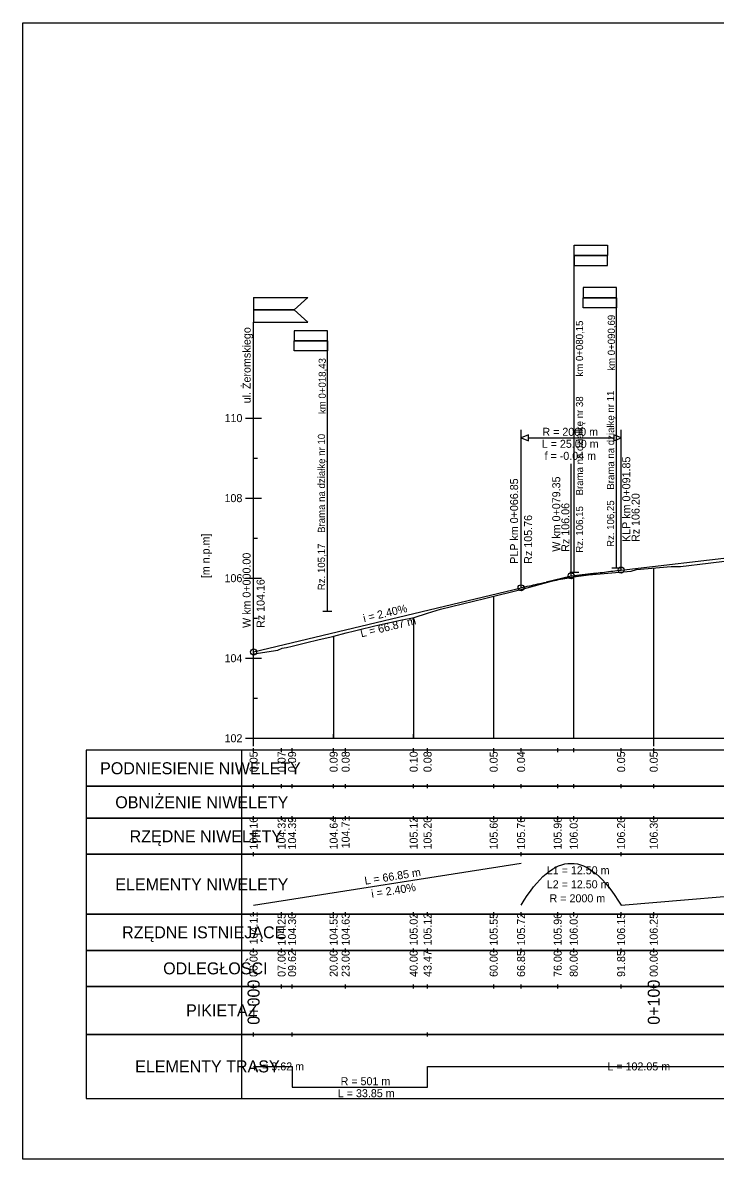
# Model space of a CAD drawing. Extents: x 7481207 to 7481727, y 5776531 to 5776815.
# Drawn here: x 7481207.5 to 7481380.5, y 5776530.9 to 5776814.9 of the extents above; entities that cross this region are included whole.
import ezdxf

# ---------------------------------------------------------------- set-up
doc = ezdxf.new("R2010")
doc.units = 0
for name, color, linetype in [('d_p_opisy_drog', 7, 'Continuous'), ('d_p_tabela', 7, 'Continuous'), ('opis niwelety', 7, 'Continuous'), ('prof_niweleta', 7, 'Continuous'), ('prof_odniesienie', 7, 'Continuous'), ('prof_os', 7, 'Continuous'), ('prof_tabela_txt', 7, 'Continuous'), ('ramka', 7, 'Continuous'), ('tabela_p', 7, 'Continuous'), ('tabela_txt_p', 7, 'Continuous'), ('teren', 7, 'Continuous'), ('zjazdy lewe', 7, 'Continuous'), ('zjazdy prawe', 7, 'Continuous')]:
    doc.layers.add(name, color=color, linetype=linetype)

msp = doc.modelspace()

# ---------------------------------------------------------------- linework, layer by layer
at = {"layer": 'd_p_opisy_drog'}
for p, q in [((7481265.15, 5776746.24), (7481265.15, 5776740.11)), ((7481265.15, 5776746.24), (7481278.69, 5776746.24)), ((7481265.15, 5776746.24), (7481265.15, 5776740.11)), ((7481265.15, 5776743.19), (7481275.25, 5776743.19)), ((7481265.15, 5776740.11), (7481278.69, 5776740.11)), ((7481265.15, 5776676.1), (7481265.15, 5776740.11))]:
    msp.add_line(p, q, dxfattribs=at)
for points in [[(7481278.69, 5776740.11), (7481275.25, 5776743.19), (7481278.69, 5776746.24)], [(7481265.15, 5776743.19), (7481265.15, 5776740.11), (7481278.69, 5776740.11), (7481275.25, 5776743.19), (7481265.15, 5776743.19)]]:
    msp.add_lwpolyline(points, dxfattribs=at)
at = {"layer": 'd_p_tabela'}
for points in [[(7481262.15, 5776633.1), (7481223.33, 5776633.1), (7481223.33, 5776624.1), (7481262.15, 5776624.1)], [(7481265.15, 5776632.6), (7481265.15, 5776633.6)], [(7481272.15, 5776632.6), (7481272.15, 5776633.6)], [(7481274.77, 5776632.6), (7481274.77, 5776633.6)], [(7481285.15, 5776632.6), (7481285.15, 5776633.6)], [(7481288.15, 5776632.6), (7481288.15, 5776633.6)], [(7481305.15, 5776632.6), (7481305.15, 5776633.6)], [(7481308.62, 5776632.6), (7481308.62, 5776633.6)], [(7481325.15, 5776632.6), (7481325.15, 5776633.6)], [(7481332, 5776632.6), (7481332, 5776633.6)], [(7481341.15, 5776632.6), (7481341.15, 5776633.6)], [(7481345.15, 5776632.6), (7481345.15, 5776633.6)], [(7481357, 5776632.6), (7481357, 5776633.6)], [(7481365.15, 5776632.6), (7481365.15, 5776633.6)], [(7481262.15, 5776624.1), (7481223.33, 5776624.1), (7481223.33, 5776616.1), (7481262.15, 5776616.1)], [(7481265.15, 5776623.6), (7481265.15, 5776624.6)], [(7481272.15, 5776623.6), (7481272.15, 5776624.6)], [(7481274.77, 5776623.6), (7481274.77, 5776624.6)], [(7481285.15, 5776623.6), (7481285.15, 5776624.6)], [(7481288.15, 5776623.6), (7481288.15, 5776624.6)], [(7481305.15, 5776623.6), (7481305.15, 5776624.6)], [(7481308.62, 5776623.6), (7481308.62, 5776624.6)], [(7481325.15, 5776623.6), (7481325.15, 5776624.6)], [(7481332, 5776623.6), (7481332, 5776624.6)], [(7481341.15, 5776623.6), (7481341.15, 5776624.6)], [(7481345.15, 5776623.6), (7481345.15, 5776624.6)], [(7481357, 5776623.6), (7481357, 5776624.6)], [(7481365.15, 5776623.6), (7481365.15, 5776624.6)], [(7481262.15, 5776616.1), (7481223.33, 5776616.1), (7481223.33, 5776607.1), (7481262.15, 5776607.1)], [(7481265.15, 5776615.6), (7481265.15, 5776616.6)], [(7481272.15, 5776615.6), (7481272.15, 5776616.6)], [(7481274.77, 5776615.6), (7481274.77, 5776616.6)], [(7481285.15, 5776615.6), (7481285.15, 5776616.6)], [(7481288.15, 5776615.6), (7481288.15, 5776616.6)], [(7481305.15, 5776615.6), (7481305.15, 5776616.6)], [(7481308.62, 5776615.6), (7481308.62, 5776616.6)], [(7481325.15, 5776615.6), (7481325.15, 5776616.6)], [(7481332, 5776615.6), (7481332, 5776616.6)], [(7481341.15, 5776615.6), (7481341.15, 5776616.6)], [(7481345.15, 5776615.6), (7481345.15, 5776616.6)], [(7481357, 5776615.6), (7481357, 5776616.6)], [(7481365.15, 5776615.6), (7481365.15, 5776616.6)], [(7481262.15, 5776607.1), (7481223.33, 5776607.1), (7481223.33, 5776592.1), (7481262.15, 5776592.1)], [(7481265.15, 5776606.6), (7481265.15, 5776607.6)], [(7481332, 5776606.6), (7481332, 5776607.6)], [(7481357, 5776606.6), (7481357, 5776607.6)], [(7481262.15, 5776592.1), (7481223.33, 5776592.1), (7481223.33, 5776583.1), (7481262.15, 5776583.1)], [(7481265.15, 5776591.6), (7481265.15, 5776592.6)], [(7481272.15, 5776591.6), (7481272.15, 5776592.6)], [(7481274.77, 5776591.6), (7481274.77, 5776592.6)], [(7481285.15, 5776591.6), (7481285.15, 5776592.6)], [(7481288.15, 5776591.6), (7481288.15, 5776592.6)], [(7481305.15, 5776591.6), (7481305.15, 5776592.6)], [(7481308.62, 5776591.6), (7481308.62, 5776592.6)], [(7481325.15, 5776591.6), (7481325.15, 5776592.6)], [(7481332, 5776591.6), (7481332, 5776592.6)], [(7481341.15, 5776591.6), (7481341.15, 5776592.6)], [(7481345.15, 5776591.6), (7481345.15, 5776592.6)], [(7481357, 5776591.6), (7481357, 5776592.6)], [(7481365.15, 5776591.6), (7481365.15, 5776592.6)], [(7481262.15, 5776583.1), (7481223.33, 5776583.1), (7481223.33, 5776574.1), (7481262.15, 5776574.1)], [(7481265.15, 5776582.6), (7481265.15, 5776583.6)], [(7481272.15, 5776582.6), (7481272.15, 5776583.6)], [(7481274.77, 5776582.6), (7481274.77, 5776583.6)], [(7481285.15, 5776582.6), (7481285.15, 5776583.6)], [(7481288.15, 5776582.6), (7481288.15, 5776583.6)], [(7481305.15, 5776582.6), (7481305.15, 5776583.6)], [(7481308.62, 5776582.6), (7481308.62, 5776583.6)], [(7481325.15, 5776582.6), (7481325.15, 5776583.6)], [(7481332, 5776582.6), (7481332, 5776583.6)], [(7481341.15, 5776582.6), (7481341.15, 5776583.6)], [(7481345.15, 5776582.6), (7481345.15, 5776583.6)], [(7481357, 5776582.6), (7481357, 5776583.6)], [(7481365.15, 5776582.6), (7481365.15, 5776583.6)], [(7481265.15, 5776573.6), (7481265.15, 5776574.6)], [(7481272.15, 5776573.6), (7481272.15, 5776574.6)], [(7481274.77, 5776573.6), (7481274.77, 5776574.6)], [(7481288.15, 5776573.6), (7481288.15, 5776574.6)], [(7481305.15, 5776573.6), (7481305.15, 5776574.6)], [(7481308.62, 5776573.6), (7481308.62, 5776574.6)], [(7481325.15, 5776573.6), (7481325.15, 5776574.6)], [(7481332, 5776573.6), (7481332, 5776574.6)], [(7481341.15, 5776573.6), (7481341.15, 5776574.6)], [(7481357, 5776573.6), (7481357, 5776574.6)], [(7481365.15, 5776573.6), (7481365.15, 5776574.6)], [(7481262.15, 5776574.1), (7481223.33, 5776574.1), (7481223.33, 5776562.1), (7481262.15, 5776562.1)], [(7481262.15, 5776562.1), (7481223.33, 5776562.1), (7481223.33, 5776546.1), (7481262.15, 5776546.1)], [(7481265.15, 5776561.6), (7481265.15, 5776562.6)], [(7481274.77, 5776561.6), (7481274.77, 5776562.6)], [(7481308.62, 5776561.6), (7481308.62, 5776562.6)]]:
    msp.add_lwpolyline(points, dxfattribs=at)
for points in [[(7481262.15, 5776624.1), (7481553.38, 5776624.1), (7481553.38, 5776633.1), (7481262.15, 5776633.1)], [(7481262.15, 5776616.1), (7481553.38, 5776616.1), (7481553.38, 5776624.1), (7481262.15, 5776624.1)], [(7481262.15, 5776607.1), (7481553.38, 5776607.1), (7481553.38, 5776616.1), (7481262.15, 5776616.1)], [(7481262.15, 5776592.1), (7481553.38, 5776592.1), (7481553.38, 5776607.1), (7481262.15, 5776607.1)], [(7481262.15, 5776583.1), (7481553.38, 5776583.1), (7481553.38, 5776592.1), (7481262.15, 5776592.1)], [(7481262.15, 5776574.1), (7481553.38, 5776574.1), (7481553.38, 5776583.1), (7481262.15, 5776583.1)], [(7481262.15, 5776562.1), (7481553.38, 5776562.1), (7481553.38, 5776574.1), (7481262.15, 5776574.1)], [(7481262.15, 5776546.1), (7481553.38, 5776546.1), (7481553.38, 5776562.1), (7481262.15, 5776562.1)]]:
    msp.add_lwpolyline(points, close=True, dxfattribs=at)
at = {"layer": 'prof_niweleta'}
for p, q in [((7481332, 5776673.7), (7481332, 5776713.14)), ((7481357, 5776678.14), (7481357, 5776713.14)), ((7481357, 5776679.14), (7481357, 5776711.14)), ((7481332, 5776673.7), (7481332, 5776705.7)), ((7481344.5, 5776676.7), (7481344.5, 5776704.7)), ((7481357, 5776678.14), (7481481.72, 5776692.49)), ((7481265.15, 5776657.66), (7481265.15, 5776685.66)), ((7481338.25, 5776675.2), (7481344.5, 5776676.7)), ((7481344.5, 5776676.7), (7481350.75, 5776677.42)), ((7481357, 5776678.14), (7481357, 5776679.14)), ((7481265.15, 5776657.66), (7481332, 5776673.7))]:
    msp.add_line(p, q, dxfattribs=at)
for points in [[(7481332, 5776711.17), (7481333.84, 5776710.41), (7481333.84, 5776711.94)], [(7481357, 5776711.17), (7481355.15, 5776711.94), (7481355.15, 5776710.41)]]:
    msp.add_lwpolyline(points, close=True, dxfattribs=at)
for points in [[(7481333.84, 5776711.17), (7481355.15, 5776711.17)], [(7481332, 5776673.7), (7481332.52, 5776673.83), (7481333.04, 5776673.95), (7481333.56, 5776674.07), (7481334.08, 5776674.19), (7481334.6, 5776674.31), (7481335.12, 5776674.43), (7481335.64, 5776674.55), (7481336.16, 5776674.66), (7481336.68, 5776674.78), (7481337.21, 5776674.89), (7481337.73, 5776675), (7481338.25, 5776675.11), (7481338.77, 5776675.22), (7481339.29, 5776675.32), (7481339.81, 5776675.43), (7481340.33, 5776675.53), (7481340.85, 5776675.63), (7481341.37, 5776675.74), (7481341.89, 5776675.84), (7481342.41, 5776675.93), (7481342.93, 5776676.03), (7481343.46, 5776676.13), (7481343.98, 5776676.22), (7481345.02, 5776676.41), (7481345.54, 5776676.5), (7481346.06, 5776676.59), (7481346.58, 5776676.67), (7481347.1, 5776676.76), (7481347.62, 5776676.84), (7481348.14, 5776676.93), (7481348.66, 5776677.01), (7481349.18, 5776677.09), (7481349.71, 5776677.17), (7481350.23, 5776677.25), (7481350.75, 5776677.33), (7481351.27, 5776677.4), (7481351.79, 5776677.48), (7481352.31, 5776677.55), (7481352.83, 5776677.62), (7481353.35, 5776677.69), (7481353.87, 5776677.76), (7481354.39, 5776677.83), (7481354.91, 5776677.89), (7481355.43, 5776677.96), (7481355.96, 5776678.02), (7481356.48, 5776678.08), (7481357, 5776678.14)]]:
    msp.add_lwpolyline(points, dxfattribs=at)
for centre in [(7481344.5, 5776676.7), (7481357, 5776678.14), (7481332, 5776673.7), (7481265.15, 5776657.66)]:
    msp.add_circle(centre, 0.75, dxfattribs=at)
at = {"layer": 'prof_odniesienie'}
for p, q in [((7481365.15, 5776636.1), (7481365.15, 5776678.62)), ((7481345.15, 5776636.1), (7481345.15, 5776676.44)), ((7481325.15, 5776636.1), (7481325.15, 5776671.61)), ((7481305.15, 5776666.26), (7481305.15, 5776636.1)), ((7481285.15, 5776661.6), (7481285.15, 5776636.1))]:
    msp.add_line(p, q, dxfattribs=at)
at = {"layer": 'prof_os'}
for p, q in [((7481263.15, 5776716.1), (7481267.15, 5776716.1)), ((7481263.15, 5776716.1), (7481267.15, 5776716.1)), ((7481265.15, 5776636.1), (7481265.15, 5776716.1)), ((7481265.15, 5776706.1), (7481266.15, 5776706.1)), ((7481263.15, 5776696.1), (7481267.15, 5776696.1)), ((7481265.15, 5776686.1), (7481266.15, 5776686.1)), ((7481263.15, 5776676.1), (7481267.15, 5776676.1)), ((7481265.15, 5776666.1), (7481266.15, 5776666.1)), ((7481263.15, 5776656.1), (7481267.15, 5776656.1)), ((7481265.15, 5776646.1), (7481266.15, 5776646.1)), ((7481265.15, 5776634.1), (7481265.15, 5776638.1)), ((7481285.15, 5776636.1), (7481285.15, 5776637.1)), ((7481305.15, 5776636.1), (7481305.15, 5776637.1)), ((7481325.15, 5776636.1), (7481325.15, 5776637.1)), ((7481345.15, 5776636.1), (7481345.15, 5776637.1)), ((7481365.15, 5776634.1), (7481365.15, 5776638.1)), ((7481263.15, 5776636.1), (7481267.15, 5776636.1)), ((7481265.15, 5776636.1), (7481550.38, 5776636.1))]:
    msp.add_line(p, q, dxfattribs=at)
at = {"layer": 'ramka'}
for points in [[(7481207.45, 5776814.89), (7481727.02, 5776814.89), (7481727.02, 5776530.89), (7481207.45, 5776530.89)], [(7481207.45, 5776814.89), (7481567.02, 5776814.89), (7481567.02, 5776530.89), (7481207.45, 5776530.89)]]:
    msp.add_lwpolyline(points, close=True, dxfattribs=at)
at = {"layer": 'tabela_p'}
for points in [[(7481265.15, 5776594.35), (7481332, 5776604.85)], [(7481332, 5776594.35), (7481332.78, 5776595.63), (7481333.56, 5776596.82), (7481334.34, 5776597.92), (7481335.12, 5776598.95), (7481335.9, 5776599.89), (7481336.68, 5776600.75), (7481337.47, 5776601.53), (7481338.25, 5776602.23), (7481339.03, 5776602.84), (7481339.81, 5776603.38), (7481340.59, 5776603.83), (7481341.37, 5776604.2), (7481342.15, 5776604.49), (7481342.93, 5776604.69), (7481343.72, 5776604.81), (7481345.28, 5776604.81), (7481346.06, 5776604.69), (7481346.84, 5776604.49), (7481347.62, 5776604.2), (7481348.4, 5776603.83), (7481349.18, 5776603.38), (7481349.97, 5776602.84), (7481350.75, 5776602.23), (7481351.53, 5776601.53), (7481352.31, 5776600.75), (7481353.09, 5776599.89), (7481353.87, 5776598.95), (7481354.65, 5776597.92), (7481355.43, 5776596.82), (7481356.22, 5776595.63), (7481357, 5776594.35)], [(7481357, 5776594.35), (7481481.72, 5776604.85)], [(7481265.15, 5776554.1), (7481274.77, 5776554.1), (7481274.77, 5776548.9), (7481308.62, 5776548.9), (7481308.62, 5776554.1), (7481410.68, 5776554.1), (7481410.68, 5776554.1), (7481503.15, 5776554.1), (7481503.15, 5776559.3), (7481523.71, 5776559.3), (7481523.71, 5776548.9), (7481542.96, 5776548.9), (7481542.96, 5776554.1), (7481550.38, 5776554.1)]]:
    msp.add_lwpolyline(points, dxfattribs=at)
at = {"layer": 'teren'}
msp.add_lwpolyline([(7481265.15, 5776657.16), (7481265.48, 5776657.21), (7481266.3, 5776657.38), (7481271.18, 5776658.09), (7481272.28, 5776658.63), (7481272.75, 5776658.71), (7481273.4, 5776658.81), (7481274.77, 5776659.13), (7481278.16, 5776659.93), (7481281.54, 5776660.74), (7481284.93, 5776661.54), (7481285.17, 5776661.6), (7481288.31, 5776662.43), (7481290.34, 5776662.96), (7481291.7, 5776663.3), (7481295.08, 5776664.13), (7481296.52, 5776664.48), (7481298.47, 5776664.89), (7481301.85, 5776665.59), (7481305.24, 5776666.28), (7481305.27, 5776666.28), (7481308.62, 5776667.34), (7481311.87, 5776668.35), (7481322.84, 5776671.05), (7481332.57, 5776673.4), (7481339.57, 5776675.37), (7481342.66, 5776676.12), (7481348.87, 5776676.93), (7481359.49, 5776677.86), (7481360.84, 5776678.26), (7481369.48, 5776678.99), (7481371.85, 5776679.04), (7481378.73, 5776679.87), (7481388.23, 5776681.04)], dxfattribs=at)
at = {"layer": 'zjazdy lewe'}
for p, q in [((7481355.84, 5776678.59), (7481355.84, 5776748.71)), ((7481355.84, 5776746.18), (7481347.55, 5776746.18)), ((7481355.84, 5776746.18), (7481347.55, 5776746.18)), ((7481283.58, 5776667.78), (7481283.58, 5776737.9)), ((7481283.58, 5776735.37), (7481275.29, 5776735.37)), ((7481283.58, 5776735.37), (7481275.29, 5776735.37)), ((7481356.97, 5776678.59), (7481354.72, 5776678.59)), ((7481284.71, 5776667.78), (7481282.46, 5776667.78))]:
    msp.add_line(p, q, dxfattribs=at)
for points in [[(7481355.84, 5776746.18), (7481355.84, 5776748.71), (7481347.55, 5776748.71), (7481347.55, 5776746.18)], [(7481355.84, 5776746.18), (7481355.84, 5776743.68), (7481347.55, 5776743.68), (7481347.55, 5776746.18)], [(7481283.58, 5776735.37), (7481283.58, 5776737.9), (7481275.29, 5776737.9), (7481275.29, 5776735.37)], [(7481283.58, 5776735.37), (7481283.58, 5776732.87), (7481275.29, 5776732.87), (7481275.29, 5776735.37)]]:
    msp.add_lwpolyline(points, close=True, dxfattribs=at)
at = {"layer": 'zjazdy prawe'}
for p, q in [((7481345.3, 5776677.55), (7481345.3, 5776759.3)), ((7481345.3, 5776756.77), (7481353.59, 5776756.77)), ((7481345.3, 5776756.77), (7481353.59, 5776756.77)), ((7481346.42, 5776677.55), (7481344.17, 5776677.55))]:
    msp.add_line(p, q, dxfattribs=at)
for points in [[(7481345.3, 5776756.77), (7481345.3, 5776759.3), (7481353.59, 5776759.3), (7481353.59, 5776756.77)], [(7481345.3, 5776756.77), (7481345.3, 5776754.27), (7481353.59, 5776754.27), (7481353.59, 5776756.77)]]:
    msp.add_lwpolyline(points, close=True, dxfattribs=at)

# ---------------------------------------------------------------- texts
at = {"layer": 'd_p_opisy_drog'}
for s, p in [('km 0+090,69', (7481355.46, 5776727.92)), ('km 0+080,15', (7481347.5, 5776726.48)), ('km 0+018,43', (7481283.2, 5776717.11)), ('Rz. 106,25    Brama na działkę nr 11', (7481355.26, 5776683.9)), ('Rz. 106,15    Brama na działkę nr 38', (7481347.5, 5776682.46)), ('Rz. 105,17    Brama na działkę nr 10', (7481283, 5776673.09))]:
    msp.add_text(s, height=1.8, rotation=90, dxfattribs=at).set_placement(p)
at = {"layer": 'opis niwelety'}
msp.add_text('ul. Żeromskiego', height=2, rotation=90, dxfattribs=at).set_placement((7481264.41, 5776719.79))
at = {"layer": 'prof_niweleta'}
for s, p in [('R = 2000 m', (7481337.33, 5776711.67)), ('L = 25.00 m', (7481337.17, 5776708.67)), ('f = -0.04 m', (7481337.87, 5776705.67))]:
    msp.add_text(s, height=2, dxfattribs=at).set_placement(p)
for s, rotation, p in [('KLP km 0+091.85', 90, (7481359.29, 5776685.14)), ('PLP km 0+066.85', 90, (7481331.25, 5776679.7)), ('W km 0+079.35', 90, (7481341.79, 5776682.7)), ('Rz 106.20', 90, (7481361.61, 5776685.14)), ('Rz 106.06', 90, (7481344.06, 5776682.7)), ('Rz 105.76', 90, (7481334.75, 5776679.7)), ('W km 0+000.00', 90, (7481264.4, 5776663.66)), ('Rz 104.16', 90, (7481267.9, 5776663.66)), ('i = 2.40%', 13.4957, (7481292.78, 5776665.06)), ('L = 66.87 m', 13.4957, (7481292.09, 5776661.3))]:
    msp.add_text(s, height=2, rotation=rotation, dxfattribs=at).set_placement(p)
at = {"layer": 'prof_os'}
for s, p in [('110', (7481257.89, 5776715.1)), ('110', (7481257.89, 5776715.1)), ('108', (7481257.88, 5776695.1)), ('106', (7481257.88, 5776675.1)), ('104', (7481257.89, 5776655.1)), ('102', (7481257.89, 5776635.1))]:
    msp.add_text(s, height=2, dxfattribs=at).set_placement(p)
msp.add_text('[m n.p.m]', height=2, rotation=90, dxfattribs=at).set_placement((7481254.15, 5776676.1))
at = {"layer": 'prof_tabela_txt'}
msp.add_text(' OBNIŻENIE NIWELETY ', height=3, dxfattribs=at).set_placement((7481229.47, 5776618.6))
for s, p in [('0+000', (7481266.65, 5776564.5)), ('0+100', (7481366.65, 5776564.5))]:
    msp.add_text(s, height=3, rotation=90, dxfattribs=at).set_placement(p)
at = {"layer": 'tabela_txt_p'}
for s, rotation, p in [('0.05', 90, (7481266.15, 5776627.61)), ('0.07', 90, (7481273.15, 5776627.62)), ('0.09', 90, (7481275.77, 5776627.62)), ('0.09', 90, (7481286.15, 5776627.62)), ('0.08', 90, (7481289.15, 5776627.62)), ('0.10', 90, (7481306.15, 5776627.63)), ('0.08', 90, (7481309.62, 5776627.62)), ('0.05', 90, (7481326.15, 5776627.61)), ('0.04', 90, (7481333, 5776627.63)), ('0.05', 90, (7481358, 5776627.61)), ('0.05', 90, (7481366.15, 5776627.61)), ('104.16', 90, (7481266.15, 5776608.29)), ('104.32', 90, (7481273.15, 5776608.31)), ('104.39', 90, (7481275.77, 5776608.29)), ('104.64', 90, (7481286.15, 5776608.3)), ('104.71', 90, (7481289.15, 5776608.58)), ('105.12', 90, (7481306.15, 5776608.31)), ('105.20', 90, (7481309.62, 5776608.3)), ('105.60', 90, (7481326.15, 5776608.3)), ('105.76', 90, (7481333, 5776608.29)), ('105.96', 90, (7481342.15, 5776608.29)), ('106.03', 90, (7481346.15, 5776608.29)), ('106.20', 90, (7481358, 5776608.3)), ('106.30', 90, (7481366.15, 5776608.3)), ('L = 66.85 m', 8.9268, (7481293.03, 5776599.49)), ('i = 2.40%', 8.9268, (7481294.72, 5776596.22)), ('104.11', 90, (7481266.15, 5776584.58)), ('104.25', 90, (7481273.15, 5776584.28)), ('104.30', 90, (7481275.77, 5776584.3)), ('104.55', 90, (7481286.15, 5776584.28)), ('104.63', 90, (7481289.15, 5776584.29)), ('105.02', 90, (7481306.15, 5776584.31)), ('105.12', 90, (7481309.62, 5776584.31)), ('105.55', 90, (7481326.15, 5776584.28)), ('105.72', 90, (7481333, 5776584.31)), ('105.96', 90, (7481342.15, 5776584.29)), ('106.03', 90, (7481346.15, 5776584.29)), ('106.15', 90, (7481358, 5776584.28)), ('106.25', 90, (7481366.15, 5776584.28)), ('00.00', 90, (7481266.15, 5776576.46)), ('07.00', 90, (7481273.15, 5776576.46)), ('09.62', 90, (7481275.77, 5776576.47)), ('20.00', 90, (7481286.15, 5776576.46)), ('23.00', 90, (7481289.15, 5776576.46)), ('40.00', 90, (7481306.15, 5776576.46)), ('43.47', 90, (7481309.62, 5776576.46)), ('60.00', 90, (7481326.15, 5776576.46)), ('66.85', 90, (7481333, 5776576.45)), ('76.00', 90, (7481342.15, 5776576.46)), ('80.00', 90, (7481346.15, 5776576.46)), ('91.85', 90, (7481358, 5776576.45)), ('00.00', 90, (7481366.15, 5776576.46))]:
    msp.add_text(s, height=2, rotation=rotation, dxfattribs=at).set_placement(p)
for s, height, p in [('    PODNIESIENIE NIWELETY ', 3, (7481222.33, 5776627.1)), (' RZĘDNE NIWELETY ', 3, (7481233.05, 5776610.1)), ('L1 = 12.50 m', 2, (7481338.42, 5776602.1)), (' ELEMENTY NIWELETY ', 3, (7481229.47, 5776598.1)), ('L2 = 12.50 m', 2, (7481338.42, 5776598.6)), ('R = 2000 m', 2, (7481339.12, 5776595.1)), (' RZĘDNE ISTNIEJĄCE ', 3, (7481231.18, 5776586.1)), (' ODLEGŁOŚCI ', 3, (7481241.43, 5776577.1)), (' PIKIETAŻ ', 3, (7481247.17, 5776566.6)), (' ELEMENTY TRASY ', 3, (7481234.44, 5776552.6)), ('L = 9.62 m', 2, (7481265.05, 5776553.1)), ('L = 102.05 m', 2, (7481353.57, 5776553.1)), ('R = 501 m', 2, (7481286.9, 5776549.4)), ('L = 33.85 m', 2, (7481286.2, 5776546.4))]:
    msp.add_text(s, height=height, dxfattribs=at).set_placement(p)

doc.saveas('drawing.dxf')
